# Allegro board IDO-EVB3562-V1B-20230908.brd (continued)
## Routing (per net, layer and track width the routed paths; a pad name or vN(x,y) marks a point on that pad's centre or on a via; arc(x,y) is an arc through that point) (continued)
LANWAKEB: length 6.4
  BOTTOM w0.127: U15.21 73.49,55.91 74.96,54.44 R161.2 74.48,53.47 74.48,52.64 74.29,52.44 74.29,51.74 74.61,51.41 R154.2
LCD_BL_PWM_GPIO0_B7_D: length 92.8
  TOP w0.127: M1.157 65.87,18.14 65.38,18.64 65.38,19.72 64.73,20.37 v1(63.44,20.37) ; v1(8.03,49.69) 10.57,47.15 10.57,44.1 10.32,43.85 8.54,43.85 7.91,43.21 v1(7.91,41.56) 7.6,41.25 R99.1
  BOTTOM w0.127: v1(63.44,20.37) 63.44,20.99 62.78,21.66 42.94,21.66 39.4,25.2 39.4,27.12 36.55,29.97 34.9,29.97 34.4,30.47 31.78,30.47 29.5,28.18 24.57,28.18 23.3,29.45 18.83,29.45 17.62,28.24 12.98,28.24 11.09,30.12 11.09,32.98 11.76,33.65 11.76,36.9 7.91,40.75 v1(7.91,41.56) ; v1(8.03,49.69) 8.03,48.73 R75.1
LCD_ON: length 15.2
  TOP w0.127: R453.1 8.41,42.9 8.41,41.41 8.15,41.15 8.15,40.17 7.9,39.91 7.33,39.91 R98.2 6.23,39.28 4.6,37.65 4.6,33.2 J43.4
LCD_PWM: length 8.9
  TOP w0.127: R99.2 6.69,40.1 4.1,37.5 4.1,34.69 J43.3
LCD_PWREN_H_GPIO0_B4_D: length 78.2
  TOP w0.127: v1(8.62,40.83) 8.62,40.27 7.62,39.28 R98.1 ; M1.154 62.87,18.55 63.12,18.8 v1(63.12,19.08)
  BOTTOM w0.127: v1(63.12,19.08) 63.12,19.31 63.91,20.09 63.91,20.88 62.88,21.91 43.05,21.91 39.66,25.3 39.66,27.22 36.66,30.22 35.01,30.22 34.51,30.72 31.68,30.72 29.39,28.43 24.68,28.43 23.4,29.71 18.73,29.71 17.51,28.49 13.08,28.49 11.35,30.22 11.35,32.88 12.01,33.54 12.01,37.01 8.62,40.4 v1(8.62,40.83)
LED0/PHYAD0: length 45.4
  TOP w0.127: v1(31.78,54.28) 31.31,54.76 31.31,56.82 33.21,58.72 33.21,68.14 35.36,70.29 35.36,71.18 35.14,71.41 33.75,71.41 C152.2 32.16,72.99 32.16,73.7 21.5,84.36 20.59,84.36 20.08,84.87 J23.11
  BOTTOM w0.127: v1(31.78,54.28) 31.78,53.37 31.53,53.12 R205.2 32.32,53.47 U17.24
LED1/GPO: length 53
  TOP w0.127: J21.13 59.98,84.8 59.98,79.18 55.91,75.11 55.91,68.68 C112.1 56.42,68.19 57.66,69.43 v1(57.66,69.6)
  BOTTOM w0.127: U15.26 71.3,57.45 70.48,56.63 70.48,55.62 70.11,55.25 68.9,55.25 68.23,54.57 65.59,54.57 65.12,55.05 65.12,58.71 67.28,60.87 67.28,65.18 66.32,66.14 65.6,66.14 64.45,67.29 59.96,67.29 v1(57.66,69.6)
LED1/PHYAD1: length 44.5
  TOP w0.127: v1(31.78,54.96) 31.78,56.93 33.46,58.61 33.46,68.03 35.62,70.19 35.62,72.02 35.21,72.42 33.75,72.42 R200.2 C150.1 32.27,73.95 25.94,80.28 25.94,84.87 27.85,86.77 29.85,86.77 J23.9
  BOTTOM w0.127: v1(31.78,54.96) 31.27,54.96 31.15,55.09 31.15,55.4 31.3,55.56 U17.25
LED2/LED1: length 53.3
  TOP w0.127: v1(66.49,65.31) 66.49,67.89 65.95,68.44 65.95,70.14 67.65,71.84 67.65,72.52 68.23,73.11 69.25,73.11 69.96,72.4 69.96,71.18 70.32,70.82 72.32,70.82 72.73,71.24 C113.1 72.73,72.21 66.17,78.77 66.17,82.13 67.11,83.06 J21.12
  BOTTOM w0.127: U15.25 71.26,57.05 70.73,56.53 70.73,55.51 70.22,55 69.01,55 68.33,54.32 65.49,54.32 64.87,54.94 64.87,58.81 67.03,60.97 67.03,64.77 v1(66.49,65.31)
MAC_MDC_: length 63.7
  BOTTOM w0.127: U17.22 33.32,52.9 33.56,52.66 33.56,50.56 34.02,50.1 35.67,50.1 38.54,47.23 43.86,47.23 49.99,41.1 61.4,41.1 66.43,46.14 76.21,46.14 77.25,47.18 77.25,47.62 78.81,49.18 78.81,50.55 79.09,50.83 80.55,50.83 81.37,51.65 C151.2 81.92,52.91 81.92,53.15 R203.2
MAC_MDIO: length 60.6
  BOTTOM w0.127: R202.2 79.76,49.72 79.76,48.88 79.41,48.52 79.41,48.39 77.85,46.84 77.37,46.84 76.36,45.83 66.56,45.83 61.53,40.8 49.83,40.8 43.68,46.95 38.41,46.95 35.57,49.79 33.84,49.79 33.08,50.55 33.08,52.51 32.91,52.68 R207.2 32.54,53.14 32.82,53.42 U17.23
MIC1_IN: length 95
  TOP w0.254: v1(92.11,37.5) 92.43,37.18 107.13,37.18 109.47,34.84 112.92,34.84 113.71,35.64 v1(120.81,35.64) ; C1049.2 88.18,36.17 v1(88.18,36.95) ; J36.1 v1(130.83,80.09)
  BOTTOM w0.254: v1(88.18,36.95) 88.18,37.38 88.42,37.62 91.68,37.62 91.81,37.5 v1(92.11,37.5) ; v1(120.81,35.64) 121.48,36.3 121.9,36.3 126.29,40.69 126.29,41.26 126.72,41.68 126.72,42.13 130.52,45.94 130.52,66.31 125.48,71.34 125.48,77.38 128.68,80.58 R388.2 129.26,82.13 129.29,82.1 D65.1 130.83,81.1 v1(130.83,80.09)
MIC2_IN: length 110.5
  TOP w0.254: v1(88.86,36.98) 88.86,36.97 88.86,35.83 C1050.2 ; v1(121.57,35.59) 121.09,35.11 113.8,35.11 113.11,34.42 109.23,34.42 106.92,36.74 91.48,36.74 v1(91.27,36.95) ; J37.1 116.18,87.33 115.63,86.77 115.63,74.76 114.49,73.62 D69.1 114.49,72.06 114.52,72.03 R387.2 114.52,68.28 114.94,67.85 130.06,67.85 v1(130.61,67.29)
  BOTTOM w0.254: v1(88.86,36.98) 88.89,36.95 v1(91.27,36.95) ; v1(130.61,67.29) 130.95,66.95 130.95,45.74 127.1,41.88 127.1,41.53 126.77,41.2 126.77,40.45 121.91,35.59 v1(121.57,35.59)
MIPI_CSI1_RX0_D2N: length 31.4
  TOP w0.102: v1(19.86,5) 19.58,5.29 19.58,5.78 19.71,5.9 J19.11
  BOTTOM w0.102: v1(19.86,5) 19.67,5.2 19.67,5.34 19.8,5.47 20.82,5.47 21.49,4.79 36.04,4.79 36.77,5.52 43.65,5.52 46.28,8.15 46.28,8.38 46.43,8.53 R1175.5
MIPI_CSI1_RX0_D2P: length 31.5
  TOP w0.102: J19.12 19.21,5.9 19.33,5.78 19.33,5.27 v1(19.06,5)
  BOTTOM w0.102: v1(19.06,5) 19.41,5.36 19.41,5.44 19.69,5.72 20.92,5.72 21.6,5.05 35.94,5.05 36.67,5.77 43.54,5.77 46.02,8.25 46.02,8.38 45.88,8.53 R1175.6
MIPI_CSI1_RX0_D3N: length 32.3
  TOP w0.102: v1(18.36,5.01) 18.08,5.28 18.08,5.78 18.21,5.9 J19.14
  BOTTOM w0.102: R1175.7 45.38,8.53 45.23,8.38 45.23,8.17 43.32,6.26 36.47,6.26 35.74,5.53 21.8,5.53 21.12,6.21 18.5,6.21 18.08,5.79 18.08,5.22 18.3,5.01 v1(18.36,5.01)
MIPI_CSI1_RX0_D3P: length 32.3
  TOP w0.102: v1(17.55,5.01) 17.83,5.28 17.83,5.78 17.71,5.9 J19.15
  BOTTOM w0.102: v1(17.55,5.01) 17.66,5.01 17.83,5.18 17.83,5.89 18.39,6.46 21.23,6.46 21.9,5.78 35.63,5.78 36.36,6.51 43.21,6.51 44.97,8.27 44.97,8.38 44.83,8.53 R1175.8
MIPI_CSI2_RX0_D2N: length 2.8
  TOP w0.102: J18.11 45.21,7.41 45.32,7.53 45.49,7.53 46.36,8.4 46.36,8.8 46.43,8.86 R1176.8
MIPI_CSI2_RX0_D2P: length 3
  TOP w0.102: J18.12 44.71,7.27 45.22,7.78 45.39,7.78 46.11,8.5 46.11,8.58 45.88,8.82 R1176.7
MIPI_CSI2_RX0_D3N: length 3.4
  TOP w0.102: J18.14 43.71,7.18 43.59,7.31 43.59,7.41 44.26,8.08 44.84,8.08 45.24,8.49 45.24,8.69 45.38,8.83 R1176.6
MIPI_CSI2_RX0_D3P: length 3.4
  TOP w0.102: J18.15 43.21,7.19 43.33,7.31 43.33,7.52 44.15,8.34 44.73,8.34 44.99,8.6 44.99,8.69 44.83,8.86 R1176.5
MIPI_CSI_RX0_CLK0N: length 13.1
  TOP w0.102: v1(48.29,7.7) 48.21,7.62 J18.5 ; M1.137 45.87,17.55 45.5,17.18 45.5,17.03 47.1,15.43 47.1,14.11 48.11,13.09 48.11,9.95 47.74,9.58 47.74,9.4 v1(48.02,9.13)
  BOTTOM w0.102: v1(48.02,9.13) 47.74,8.85 47.74,8.59 48.04,8.29 48.04,7.96 v1(48.29,7.7)
MIPI_CSI_RX0_CLK0P: length 13.1
  TOP w0.102: M1.136 44.87,17.55 45.24,17.18 45.24,16.93 46.85,15.33 46.85,14 47.86,12.99 47.86,10.06 47.49,9.68 47.49,9.4 v1(47.21,9.13) ; v1(47.53,7.7) 47.71,7.53 J18.6
  BOTTOM w0.102: v1(47.21,9.13) 47.49,8.85 47.49,8.48 47.78,8.18 47.78,7.96 v1(47.53,7.7)
MIPI_CSI_RX0_CLK1N: length 41.5
  TOP w0.102: J19.17 16.71,7.47 16.58,7.59 16.58,7.84 15.39,9.04 15.39,9.57 14.47,10.49 14.47,14.34 16.39,16.26 18.88,16.26 19.13,16.52 19.13,16.81 v1(19.38,17.06) ; v1(39.77,19.47) 39.5,19.2 39.5,18.68 39.87,18.31 M1.131
  BOTTOM w0.102: v1(39.77,19.47) 39.5,19.19 39.5,18.75 39.23,18.47 38.33,18.47 38.07,18.72 38.07,19.85 37.95,19.97 37.58,19.97 37.47,19.86 37.47,18.72 37.21,18.47 26.9,18.47 26.78,18.35 25.46,18.35 24.79,17.68 19.31,17.68 19.11,17.48 19.11,17.33 v1(19.38,17.06)
MIPI_CSI_RX0_CLK1P: length 41.5
  TOP w0.102: J19.18 16.21,7.47 16.33,7.59 16.33,7.74 15.14,8.93 15.14,9.47 14.22,10.38 14.22,14.45 16.29,16.52 18.77,16.52 18.88,16.62 18.88,16.76 v1(18.58,17.06) ; v1(38.97,19.47) 39.25,19.18 39.25,18.65 38.87,18.27 M1.130
  BOTTOM w0.102: v1(18.58,17.06) 18.85,17.33 18.85,17.58 19.21,17.94 24.69,17.94 25.35,18.6 26.67,18.6 26.8,18.73 37.11,18.73 37.21,18.83 37.21,19.96 37.47,20.23 38.06,20.23 38.33,19.95 38.33,18.83 38.43,18.73 39.12,18.73 39.24,18.85 39.24,19.19 v1(38.97,19.47)
MIPI_CSI_RX0_D0N: length 12.5
  TOP w0.102: J18.2 49.71,7.47 49.59,7.59 49.59,8.52 49.74,8.68 49.74,8.93 49.59,9.08 49.59,9.34 49.74,9.49 49.74,9.74 49.59,9.9 49.59,11.6 50.68,12.69 50.68,16.06 49.61,17.13 49.61,17.23 49.87,17.49 M1.141
MIPI_CSI_RX0_D0P: length 12.5
  TOP w0.102: J18.3 49.21,7.47 49.33,7.59 49.33,11.7 50.43,12.8 50.43,15.96 49.36,17.02 49.36,17.28 49.28,17.36 49,17.36 48.87,17.49 M1.140
MIPI_CSI_RX0_D1N: length 14.8
  TOP w0.102: J18.8 46.71,7.23 46.59,7.35 46.59,7.58 47.3,8.29 48.41,8.29 48.85,8.73 48.85,11.9 49.94,13 49.94,15.3 49.46,15.78 48.84,15.78 47.5,17.12 47.5,17.32 47.87,17.7 M1.139
MIPI_CSI_RX0_D1P: length 14.8
  TOP w0.102: J18.9 46.21,7.22 46.33,7.34 46.33,7.68 47.19,8.55 48.31,8.55 48.6,8.83 48.6,12.01 49.69,13.1 49.69,15.19 49.36,15.53 48.74,15.53 47.24,17.02 47.24,17.29 46.87,17.66 M1.138
MIPI_CSI_RX0_D2N: length 10.3
  TOP w0.102: M1.135 43.87,17.63 43.59,17.36 43.59,17.28 45.45,15.43 45.45,13.22 46.38,12.29 46.38,10.96 v1(46.64,10.7) 46.64,10.68 46.43,10.47 R1176.1
  BOTTOM w0.102: v1(46.64,10.7) 46.43,10.48 R1176.1
MIPI_CSI_RX0_D2P: length 10.3
  TOP w0.102: M1.134 42.87,17.62 43.11,17.38 43.26,17.38 43.34,17.3 43.34,17.18 45.19,15.32 45.19,13.11 46.13,12.18 46.13,10.96 45.87,10.7 v1(45.87,10.69) 45.85,10.69 45.88,10.67 R1176.2
  BOTTOM w0.102: v1(45.87,10.69) 45.88,10.68 R1176.2
MIPI_CSI_RX0_D3N: length 10.7
  TOP w0.102: R1176.3 45.38,10.32 45.12,10.57 v1(45.12,10.7) 44.86,10.95 44.86,11.82 42.3,14.39 42.3,15.91 41.38,16.82 41.38,17.23 41.87,17.72 M1.133
  BOTTOM w0.102: v1(45.12,10.7) 45.12,10.57 45.38,10.32 R1176.3
MIPI_CSI_RX0_D3P: length 10.8
  TOP w0.102: M1.132 40.87,17.69 41.13,17.43 41.13,16.72 42.04,15.8 42.04,14.28 44.61,11.72 44.61,10.95 v1(44.36,10.7) 44.36,10.57 44.83,10.1 R1176.4
  BOTTOM w0.102: v1(44.36,10.7) 44.36,10.57 44.83,10.1 R1176.4
MIPI_CSI_RX1_CLK0N: length 53.4
  TOP w0.102: v1(35.8,23.28) 35.98,23.28 36.08,23.38 36.08,23.71 36.18,23.81 36.65,23.81 36.75,23.71 36.75,23.33 36.9,23.19 37.57,23.19 ; J20.17 2.64,18.21 2.57,18.14 2.45,18.14 2.39,18.2 2.39,22.4 3.26,23.27 6.23,23.27 7.17,22.33 11.61,22.33 15.09,23.07 15.89,23.07 v1(16.16,22.79)
  BOTTOM w0.102: v1(16.16,22.79) 16.44,23.07 16.69,23.07 16.92,23.3 16.92,24.31 17.3,24.69 18.7,24.69 19.25,24.13 19.25,21.85 20.29,20.81 23.71,20.81 24.95,22.05 30.87,22.05 31.12,22.31 31.12,23.25 31.22,23.35 31.63,23.35 31.73,23.25 31.73,22.31 31.98,22.05 32.6,22.05 32.85,22.31 32.85,23.88 32.95,23.99 33.36,23.99 33.46,23.88 33.46,22.31 33.71,22.05 34.37,22.05 34.63,22.31 34.63,23.05 35.15,23.56 35.52,23.56 v1(35.8,23.28)
MIPI_CSI_RX1_CLK0P: length 53.4
  TOP w0.102: v1(35.8,24.09) 35.82,24.06 36.79,24.06 36.91,24.19 37.57,24.19 ; J20.15 2.62,17.81 2.55,17.89 2.35,17.89 2.14,18.1 2.14,22.51 3.15,23.53 6.34,23.53 7.28,22.59 11.58,22.59 15.06,23.32 15.89,23.32 v1(16.16,23.6)
  BOTTOM w0.102: v1(35.8,24.09) 35.52,23.81 35.04,23.81 34.38,23.15 34.38,22.42 34.27,22.31 33.81,22.31 33.71,22.41 33.71,23.99 33.46,24.24 32.85,24.24 32.6,23.99 32.6,22.41 32.49,22.31 32.09,22.31 31.99,22.41 31.99,23.36 31.74,23.61 31.12,23.61 30.87,23.36 30.87,22.41 30.77,22.31 24.85,22.31 23.6,21.06 20.4,21.06 19.5,21.96 19.5,24.24 18.8,24.94 17.19,24.94 16.67,24.42 16.67,23.4 16.59,23.32 16.44,23.32 v1(16.16,23.6)
MIPI_CSI_RX1_D0N: length 51.9
  TOP w0.102: 37.57,19.19 36.94,19.19 36.82,19.3 36.82,19.65 36.69,19.79 36.33,19.79 36.2,19.67 36.2,19.36 36.12,19.28 v1(35.8,19.28) ; J20.13 2.55,17.41 2.5,17.36 2.12,17.36 1.79,17.69 1.79,22.84 2.96,24.01 5.62,24.01 7.51,25.89 8.47,25.89 9.28,26.7 11.87,26.7 11.97,26.6 11.97,25.53 12.22,25.28 12.84,25.28 13.09,25.53 13.09,26.6 13.19,26.7 14.35,26.7 16.82,24.24 16.82,23.76 17.04,23.54 17.4,23.18 17.4,22.28 v1(17.13,22)
  BOTTOM w0.102: v1(35.8,19.28) 35.57,19.51 34.68,19.51 34.52,19.67 26.47,19.67 26.14,19.34 19.46,19.34 17.4,21.4 17.4,21.73 v1(17.13,22)
MIPI_CSI_RX1_D0P: length 52.2
  TOP w0.102: J20.11 2.59,17.01 2.5,17.1 2.01,17.1 1.53,17.58 1.53,22.94 2.85,24.26 5.52,24.26 7.4,26.15 8.37,26.15 9.18,26.96 11.98,26.96 12.23,26.71 12.23,25.64 12.33,25.53 12.73,25.53 12.84,25.64 12.84,26.71 13.09,26.96 14.46,26.96 17.08,24.34 17.08,23.86 17.66,23.28 17.66,22.28 v1(17.93,22) ; 37.57,20.19 37.1,20.19 36.96,20.05 35.84,20.05 v1(35.8,20.09)
  BOTTOM w0.102: v1(35.8,20.09) 35.8,19.85 35.72,19.77 34.78,19.77 34.63,19.92 26.37,19.92 26.04,19.59 19.57,19.59 17.66,21.5 17.66,21.73 v1(17.93,22)
MIPI_CSI_RX1_D1N: length 52.1
  TOP w0.102: J20.9 2.67,16.61 2.6,16.54 1.86,16.54 1.15,17.25 1.15,23.2 2.74,24.79 6.56,26 7.2,26.63 8.11,26.63 8.92,27.44 15.12,27.44 17.97,24.59 17.97,24.34 v1(17.7,24.06) ; v1(35.8,21.28) 36.02,21.28 36.12,21.39 36.12,21.67 36.25,21.8 36.58,21.8 36.7,21.68 36.7,21.28 36.79,21.19 37.57,21.19
  BOTTOM w0.102: v1(17.7,24.06) 17.97,23.79 17.97,23.5 18.51,22.26 18.51,21.55 19.99,20.07 24.01,20.07 25.26,21.32 35.16,21.32 35.4,21.56 35.52,21.56 v1(35.8,21.28)
MIPI_CSI_RX1_D1P: length 52.1
  TOP w0.102: v1(35.8,22.09) 35.83,22.05 36.76,22.05 36.89,22.19 37.57,22.19 ; J20.7 2.65,16.21 2.58,16.29 1.76,16.29 0.9,17.15 0.9,23.3 2.6,25.01 6.43,26.22 7.09,26.89 8,26.89 8.81,27.69 15.22,27.69 18.22,24.69 18.22,24.34 v1(18.5,24.06)
  BOTTOM w0.102: v1(18.5,24.06) 18.22,23.79 18.22,23.55 18.77,22.31 18.77,21.65 20.09,20.33 23.91,20.33 25.15,21.57 35.06,21.57 35.3,21.81 35.52,21.81 v1(35.8,22.09)
MIPI_CSI_RX1_D2N: length 51.8
  TOP w0.102: 37.57,25.19 37.14,25.19 36.89,25.43 35.95,25.43 v1(35.8,25.28) ; v1(21.47,22.38) 21.75,22.11 21.75,21.85 22,21.6 23.04,21.6 23.38,21.26 23.38,21.07 23.2,20.89 21.6,20.89 21.33,20.62 21.33,20.05 21.6,19.77 23.19,19.77 23.38,19.59 23.38,19.34 22.74,18.7 14.35,18.7 11.42,15.78 8.91,15.78 7.69,14.56 7.12,14.56 6.87,14.31 6.87,13.24 6.77,13.14 6.36,13.14 6.26,13.24 6.26,14.31 6.01,14.56 4.56,14.56 3.78,15.34 3.28,15.34 3.21,15.41 J20.3
  BOTTOM w0.102: v1(35.8,25.28) 35.52,25.56 35.39,25.56 34.61,24.77 32.01,24.77 31.33,24.09 30.61,24.09 29.31,22.79 24.65,22.79 23.4,21.55 22.1,21.55 21.75,21.9 21.75,22.11 v1(21.47,22.38)
MIPI_CSI_RX1_D2P: length 52.1
  TOP w0.102: 37.57,26.19 37.18,26.19 36.96,25.97 36.96,25.86 36.79,25.69 36.2,25.69 v1(35.8,26.09) ; J20.1 3.21,15.01 3.28,15.09 3.67,15.09 4.45,14.31 5.91,14.31 6.01,14.21 6.01,13.14 6.26,12.89 6.88,12.89 7.13,13.14 7.13,14.21 7.23,14.31 7.8,14.31 9.01,15.53 11.53,15.53 14.45,18.45 22.84,18.45 23.63,19.24 23.63,19.69 23.29,20.03 21.71,20.03 21.58,20.16 21.58,20.51 21.71,20.64 23.3,20.64 23.63,20.96 23.63,21.37 23.15,21.85 22.11,21.85 22,21.96 22,22.11 v1(22.28,22.38)
  BOTTOM w0.102: v1(22.28,22.38) 22,22.11 22,22 22.21,21.8 23.3,21.8 24.54,23.05 29.2,23.05 30.5,24.35 31.22,24.35 31.91,25.03 34.5,25.03 35.29,25.81 35.52,25.81 v1(35.8,26.09)
MIPI_CSI_RX1_D3N: length 51.8
  TOP w0.102: v1(35.8,27.28) 36.12,27.28 36.23,27.39 36.23,27.69 36.33,27.8 36.71,27.8 36.79,27.72 36.79,27.29 36.89,27.19 37.57,27.19 ; v1(20.08,22.8) 20.36,23.07 20.5,23.07 20.59,22.98 20.59,19.63 20.43,19.46 19.77,19.46 19.67,19.57 19.67,20 19.84,20.18 19.84,21.04 19.55,21.33 18.8,21.33 18.55,21.08 18.55,19.57 18.45,19.46 14.07,19.46 11.12,16.52 8.6,16.52 7.43,15.34 5.26,15.34 5.19,15.41 J20.4
  BOTTOM w0.102: v1(20.08,22.8) 20.36,23.07 21.75,23.07 22.2,23.53 22.66,23.53 23.3,22.89 23.71,22.89 24.34,23.53 29,23.53 31.21,25.73 31.21,26.93 31.35,27.08 31.73,27.08 31.83,26.97 31.83,25.76 32.08,25.51 32.7,25.51 32.95,25.76 32.95,26.87 33.05,26.97 33.46,26.97 33.56,26.87 33.56,25.82 33.81,25.56 34.35,25.56 34.67,25.88 34.67,26.83 35.41,27.56 35.52,27.56 v1(35.8,27.28)
MIPI_CSI_RX1_D3P: length 51.8
  TOP w0.102: 37.57,28.19 37.08,28.19 36.94,28.05 35.84,28.05 v1(35.8,28.09) ; v1(20.08,23.6) 20.36,23.33 20.61,23.33 20.84,23.09 20.84,19.52 20.53,19.21 19.67,19.21 19.41,19.46 19.41,20.1 19.59,20.28 19.59,20.93 19.44,21.08 18.91,21.08 18.81,20.98 18.81,19.46 18.55,19.21 14.17,19.21 11.22,16.26 8.71,16.26 7.53,15.09 5.26,15.09 5.19,15.01 J20.2
  BOTTOM w0.102: v1(20.08,23.6) 20.36,23.33 21.64,23.33 22.1,23.78 22.77,23.78 23.4,23.15 23.6,23.15 24.24,23.78 28.9,23.78 30.95,25.84 30.95,27.04 31.25,27.33 31.83,27.33 32.08,27.08 32.08,25.86 32.19,25.76 32.59,25.76 32.69,25.86 32.69,26.97 32.94,27.22 33.56,27.22 33.81,26.97 33.81,25.92 33.92,25.81 34.25,25.81 34.42,25.99 34.42,26.93 35.3,27.81 35.52,27.81 v1(35.8,28.09)
MIPI_DSI_RST: length 89.5
  TOP w0.127: v1(8.8,67.6) 11.14,65.25 14.04,65.25 16.54,62.75 16.54,62.14 16.78,61.89 18.24,61.89 19.34,60.8 19.34,59.34 18.57,58.58 17.54,58.58 17.43,58.47 D24.6 D24.5 15.51,58.47 15.4,58.58 15.4,58.83 15.54,58.97 D24.4 D24.7 18.46,58.97 18.96,59.47 18.96,60.82 18.13,61.64 16.66,61.64 16.29,62.01 16.29,62.64 13.93,65 11.23,65 10.62,64.4 10.62,63.7 v1(9.99,63.07) 9.61,63.07 9.4,62.86 7.94,62.86 7.7,62.62 J46.16 ; R78.1 v1(40.8,69.25)
  BOTTOM w0.127: v1(40.8,69.25) 38.71,69.25 35.53,72.42 33.16,72.42 29.08,76.5 20.98,76.5 13.11,68.64 9.84,68.64 v1(8.8,67.6) ; v1(9.99,63.07) 9.33,62.41 9.33,61.41 8.74,60.82 6.05,60.82 4.79,62.08 R444.1 C93.2
MIPI_DSI_TX_CLKN/LVDS_TX_CLKN: length 90.5
  TOP w0.102: v1(43.79,39.48) 43.54,39.74 43.3,39.74 43.16,39.59 43.16,38.72 42.28,37.84 42.28,34.71 40.92,33.35 40.92,26.05 44.04,22.93 51.66,22.93 54.18,20.41 55.06,20.41 55.5,19.97 55.5,18.94 55.87,18.56 M1.147 ; v1(18.47,57.02) 18.19,57.3 17.59,57.3 17.47,57.17 D21.4 D21.7 15.66,57.17 15.58,57.25 15.58,57.32 15.48,57.42 14.93,57.42 14.49,57.87 14.49,60.48 14.09,60.88 13.11,60.88 12.75,60.52 12.75,60.37 12.83,60.28 13.35,60.28 J16.15 12.85,60.01 12.75,59.91 12.75,59.43 12.22,58.91 12.01,58.91 11.09,58.91 10.44,58.26 9.82,58.26 R1186.1
  BOTTOM w0.102: v1(43.79,39.48) 43.52,39.75 43.27,39.75 43.03,39.99 43.03,40.22 42.56,40.69 42.17,40.69 40.49,42.37 39.45,42.37 39.2,42.63 39.2,43.11 39.1,43.21 38.69,43.21 38.59,43.11 38.59,42.63 38.34,42.37 37.47,42.37 35.92,43.93 21.82,43.93 19.76,45.99 19.76,56.47 18.94,57.3 18.74,57.3 v1(18.47,57.02)
MIPI_DSI_TX_CLKP/LVDS_TX_CLKP: length 90.7
  TOP w0.102: v1(18.47,57.83) 18.19,57.55 17.59,57.55 17.47,57.67 D21.5 D21.6 15.03,57.67 14.74,57.97 14.74,60.59 14.2,61.13 13,61.13 12.18,60.31 11.92,60.31 J16.16 12.39,60.01 12.49,59.91 12.49,59.54 12.12,59.16 12.12,59.16 10.98,59.16 10.33,58.52 9.82,58.52 R1187.1 ; M1.146 54.87,18.56 55.24,18.94 55.24,19.87 54.95,20.16 54.08,20.16 51.56,22.67 43.94,22.67 40.67,25.94 40.67,33.46 42.02,34.81 42.02,37.94 42.9,38.82 42.9,39.7 43.2,39.99 43.5,39.99 v1(43.79,40.28)
  BOTTOM w0.102: v1(43.79,40.28) 43.52,40.01 43.37,40.01 43.28,40.1 43.28,40.33 42.67,40.94 42.28,40.94 40.59,42.63 39.56,42.63 39.45,42.73 39.45,43.22 39.2,43.47 38.59,43.47 38.34,43.22 38.34,42.73 38.23,42.63 37.57,42.63 36.02,44.18 21.93,44.18 20.02,46.09 20.02,56.58 19.04,57.55 18.74,57.55 v1(18.47,57.83)
MIPI_DSI_TX_D0N/LVDS_TX_D0N: length 88.6
  TOP w0.102: v1(18.32,51.46) 18.04,51.73 17.59,51.73 17.47,51.61 D20.1 D20.10 15.62,51.61 15.49,51.73 15.11,51.73 14,52.84 13.04,52.84 12.75,52.55 12.75,52.39 12.86,52.28 13.35,52.28 J16.7 12.85,52.01 12.75,51.91 12.75,51.63 12.03,50.91 11.21,50.91 8.99,53.13 8.99,53.49 R1182.1 ; v1(43.42,38.16) 43.7,37.89 44.09,37.89 44.58,37.41 44.58,34.92 42.4,32.74 42.4,26.66 44.65,24.4 54.66,24.4 55.28,23.77 55.43,23.77 55.82,24.16 56.17,24.16 56.61,23.72 56.61,23.37 56.22,22.98 56.22,22.84 56.51,22.55 56.65,22.55 57.16,23.07 57.52,23.07 57.95,22.63 57.95,22.28 57.44,21.76 57.44,21.32 59.5,19.26 59.5,18.94 59.87,18.56 M1.151
  BOTTOM w0.102: v1(18.32,51.46) 18.04,51.73 17.9,51.73 17.79,51.63 17.79,50.6 18.55,49.84 18.55,45.48 22.11,41.92 25.63,41.92 26.42,42.71 35.41,42.71 36.96,41.16 38.82,41.16 42.08,37.89 43.15,37.89 v1(43.42,38.16)
MIPI_DSI_TX_D0P/LVDS_TX_D0P: length 88.4
  TOP w0.102: M1.150 58.87,18.56 59.24,18.94 59.24,19.16 57.19,21.21 57.19,21.87 57.7,22.38 57.7,22.52 57.41,22.81 57.27,22.81 56.75,22.3 56.4,22.3 55.96,22.73 55.96,23.09 56.35,23.48 56.35,23.62 56.06,23.91 55.92,23.91 55.53,23.52 55.18,23.52 54.55,24.15 44.55,24.15 42.14,26.55 42.14,32.85 44.32,35.03 44.32,37.3 43.99,37.63 43.7,37.63 v1(43.42,37.36) ; R1183.1 9.24,53.49 9.24,53.23 11.31,51.16 11.92,51.16 12.49,51.74 12.49,51.91 12.39,52.01 J16.8 11.92,52.31 12.15,52.31 12.94,53.09 14.11,53.09 15.21,51.99 15.49,51.99 15.62,52.11 D20.9 D20.2 17.47,52.11 17.59,51.99 18.04,51.99 v1(18.32,52.26)
  BOTTOM w0.102: v1(18.32,52.26) 18.04,51.99 17.79,51.99 17.53,51.73 17.53,50.49 18.29,49.74 18.29,45.38 22,41.66 25.73,41.66 26.52,42.46 35.31,42.46 36.86,40.9 38.71,40.9 41.98,37.63 43.15,37.63 v1(43.42,37.36)
MIPI_DSI_TX_D1N/LVDS_TX_D1N: length 89.3
  TOP w0.102: M1.149 57.87,18.56 57.5,18.94 57.5,19.64 56.46,20.68 56.2,20.68 55.95,20.68 55.66,20.96 55.66,21.11 56.11,21.55 56.11,21.91 55.6,22.42 55.24,22.42 54.92,22.1 54.78,22.1 54.49,22.39 54.49,22.53 54.81,22.85 54.81,23.21 54.35,23.66 44.35,23.66 41.66,26.35 41.66,33.05 43.47,34.86 43.47,35.57 v1(43.74,35.85) ; v1(18.32,52.98) 18.05,53.26 17.62,53.26 17.47,53.11 D20.4 D20.7 15.62,53.11 15.37,53.36 15.16,53.36 14.64,53.88 14.64,54.13 13.84,54.93 12.99,54.93 12.71,54.65 12.71,54.44 12.81,54.34 13.29,54.34 J16.9 12.85,54.01 12.75,53.91 12.75,53.59 12.03,52.86 11.21,52.86 10.69,53.38 10.54,53.75 10.54,54.16 10.16,56.28 9.95,56.48 9.82,56.48 R1184.1
  BOTTOM w0.102: v1(43.74,35.85) 43.47,36.12 43.47,36.43 43.17,36.74 42.2,36.74 38.51,40.42 36.66,40.42 35.11,41.97 26.72,41.97 25.93,41.18 21.8,41.18 17.81,45.18 17.81,49.54 17.05,50.29 17.05,53.12 17.2,53.26 18.05,53.26 v1(18.32,52.98)
MIPI_DSI_TX_D1P/LVDS_TX_D1P: length 89.4
  TOP w0.102: v1(18.32,53.79) 18.05,53.51 17.57,53.51 17.47,53.61 D20.5 D20.6 15.27,53.61 14.89,53.99 14.89,54.24 13.95,55.18 12.88,55.18 12.04,54.34 11.95,54.34 J16.10 12.39,54.01 12.49,53.91 12.49,53.69 11.92,53.12 11.31,53.12 10.9,53.52 10.79,53.8 10.79,54.18 10.39,56.4 10.05,56.74 9.82,56.74 R1185.1 ; v1(42.94,35.85) 43.21,35.57 43.21,34.96 41.41,33.15 41.41,26.25 44.24,23.41 54.24,23.41 54.56,23.1 54.56,22.96 54.24,22.64 54.24,22.28 54.67,21.85 55.03,21.85 55.35,22.17 55.49,22.17 55.85,21.8 55.85,21.66 55.41,21.21 55.41,20.86 55.84,20.42 56.2,20.42 56.35,20.42 57.24,19.53 57.24,18.94 56.87,18.56 M1.148
  BOTTOM w0.102: v1(18.32,53.79) 18.05,53.51 17.09,53.51 16.8,53.22 16.8,50.19 17.55,49.43 17.55,45.07 21.7,40.93 26.04,40.93 26.83,41.72 35,41.72 36.55,40.16 38.41,40.16 42.09,36.48 43.06,36.48 43.21,36.33 43.21,36.12 v1(42.94,35.85)
MIPI_DSI_TX_D2N/LVDS_TX_D2N: length 89.8
  TOP w0.102: R1188.1 9.5,59.86 9.74,60.1 9.84,60.1 v1(10.12,59.82) ; v1(18.32,55.52) 18.04,55.8 17.59,55.8 17.47,55.67 D21.1 D21.10 15.62,55.67 15.49,55.8 15.13,55.8 14.08,56.85 13.11,56.85 12.75,56.49 12.75,56.11 12.85,56.01 J16.11 ; v1(42.32,39.25) 42.05,39.53 41.79,39.53 41.54,39.28 41.54,35.01 40.19,33.66 40.19,25.74 43.74,22.19 51.23,22.19 53.5,19.93 53.5,18.94 53.87,18.56 M1.145
  BOTTOM w0.102: v1(10.12,59.82) 10.28,59.82 10.73,59.38 10.73,58.66 10.47,58.41 10.47,55.56 11.13,54.9 12.2,54.9 12.75,55.44 12.75,55.91 12.85,56.01 J16.11 ; v1(42.32,39.25) 42.05,39.53 41.13,39.53 40.52,40.14 40.52,40.72 40.7,40.9 40.7,41.05 40.41,41.33 40.27,41.33 40.12,41.18 39.47,41.18 39.02,41.64 37.16,41.64 35.61,43.19 25.74,43.19 25.64,43.09 25.64,42.83 25.39,42.58 24.77,42.58 24.52,42.83 24.52,43.09 24.42,43.19 24.02,43.19 23.91,43.09 23.91,42.83 23.66,42.58 23.05,42.58 22.8,42.83 22.8,43.09 22.69,43.19 21.52,43.19 19.03,45.68 19.03,55.5 18.73,55.8 18.59,55.8 v1(18.32,55.52)
MIPI_DSI_TX_D2P/LVDS_TX_D2P: length 90.3
  TOP w0.102: M1.144 52.87,18.56 53.24,18.94 53.24,19.82 51.13,21.94 43.63,21.94 39.93,25.64 39.93,33.76 41.29,35.12 41.29,39.38 41.69,39.78 42.05,39.78 v1(42.32,40.06) ; v1(10.12,60.63) 9.84,60.35 9.76,60.35 R1189.1 ; v1(18.32,56.33) 18.04,56.05 17.59,56.05 17.47,56.18 D21.2 D21.9 15.62,56.18 15.49,56.05 15.24,56.05 14.18,57.11 13.01,57.11 12.49,56.59 12.49,56.28 12.22,56.01 J16.12
  BOTTOM w0.102: v1(42.32,40.06) 42.05,39.78 41.23,39.78 40.77,40.24 40.77,40.62 40.96,40.8 40.96,41.15 40.52,41.59 40.17,41.59 40.01,41.43 39.58,41.43 39.12,41.89 37.27,41.89 35.72,43.45 25.64,43.45 25.39,43.2 25.39,42.93 25.29,42.83 24.88,42.83 24.78,42.93 24.78,43.2 24.53,43.45 23.91,43.45 23.66,43.2 23.66,42.93 23.56,42.83 23.15,42.83 23.05,42.93 23.05,43.2 22.8,43.45 21.62,43.45 19.28,45.79 19.28,55.61 18.84,56.05 18.59,56.05 v1(18.32,56.33) ; v1(10.12,60.63) 10.13,60.63 10.73,60.03 10.73,59.74 10.98,59.48 10.98,58.55 10.73,58.3 10.73,55.66 11.24,55.15 12.1,55.15 12.49,55.55 12.49,55.82 12.31,56.01 J16.12
MIPI_DSI_TX_D3N/LVDS_TX_D3N: length 90.3
  TOP w0.102: v1(18.32,59.82) 18.04,60.09 17.59,60.09 17.47,59.97 D24.9 D24.2 15.81,59.97 15.69,60.09 15.47,60.09 15.22,60.34 15.22,61.83 14.16,62.89 12.86,62.89 12.63,62.66 12.63,62.49 12.78,62.34 13.29,62.34 J16.17 12.85,62.01 12.75,61.91 12.75,61.56 12.05,60.87 11.18,60.87 10.23,61.82 9.82,61.82 R1190.1 ; v1(43.47,41.22) 43.19,41.49 41.87,41.49 40.69,40.31 40.69,35.37 39.45,34.12 39.45,25.44 43.54,21.34 50.35,21.34 51.5,20.2 51.5,18.94 51.87,18.56 M1.143
  BOTTOM w0.102: v1(43.47,41.22) 43.19,41.49 42.41,41.49 40.5,43.4 40.08,43.4 39.44,44.04 36.84,44.04 36.22,44.67 22.74,44.67 20.5,46.91 20.5,56.91 19.72,57.69 19.72,59.67 19.29,60.09 18.59,60.09 v1(18.32,59.82)
MIPI_DSI_TX_D3P/LVDS_TX_D3P: length 90.3
  TOP w0.102: v1(43.47,42.02) 43.19,41.75 41.77,41.75 40.44,40.42 40.44,35.47 39.2,34.23 39.2,25.33 43.44,21.09 50.25,21.09 51.24,20.09 51.24,18.94 50.87,18.56 M1.142 ; v1(18.32,60.62) 18.04,60.35 17.59,60.35 17.47,60.47 D24.10 D24.1 15.84,60.47 15.72,60.35 15.58,60.35 15.48,60.45 15.48,61.93 14.26,63.14 12.76,63.14 J16.18 12.39,62.01 12.49,61.91 12.49,61.67 11.95,61.12 11.29,61.12 10.34,62.07 9.82,62.07 R1191.1
  BOTTOM w0.102: v1(18.32,60.62) 18.59,60.35 19.4,60.35 19.97,59.77 19.97,57.8 20.76,57.01 20.76,47.01 22.85,44.92 36.33,44.92 36.95,44.3 39.54,44.3 40.18,43.65 40.61,43.65 42.52,41.75 43.19,41.75 v1(43.47,42.02)
MIPI_TX_BL_PWM: length 2.3
  BOTTOM w0.127: U10.4 7.21,50.32 7.21,50.32 R82.2 7.21,49.44 7.27,49.38 R75.2
MIPI_TX_CLKN: length 2.4
  TOP w0.102: J46.8 7.34,58.62 7.47,58.74 7.62,58.74 8.08,58.28 8.27,58.28 R1186.2
MIPI_TX_CLKP: length 2.4
  TOP w0.102: J46.9 7.34,59.12 7.47,58.99 7.72,58.99 8.18,58.53 8.3,58.53 R1187.2
MIPI_TX_D0N: length 3.3
  TOP w0.102: R1182.2 8.99,55.03 8.99,55.18 8.88,55.28 7.8,55.28 7.34,55.74 7.23,55.74 7.1,55.62 J46.2
MIPI_TX_D0P: length 3.7
  TOP w0.102: R1183.2 9.24,55.03 9.24,55.28 8.99,55.53 7.91,55.53 7.45,55.99 7.19,55.99 7.07,56.12 J46.3
MIPI_TX_D1N: length 2.7
  TOP w0.102: R1184.2 8.3,56.47 8,56.47 7.7,56.77 7.7,57.08 7.54,57.24 7.33,57.24 7.2,57.12 J46.5
MIPI_TX_D1P: length 2.7
  TOP w0.102: J46.6 7.22,57.62 7.34,57.49 7.65,57.49 7.96,57.18 7.96,56.88 8.11,56.73 8.27,56.73 R1185.2
MIPI_TX_D2N: length 2.6
  TOP w0.102: R1188.2 8.6,59.97 8.48,60.09 7.87,60.09 7.59,60.36 7.4,60.36 7.16,60.12 J46.11
MIPI_TX_D2P: length 2.3
  TOP w0.102: R1189.2 8.33,60.35 7.97,60.35 7.7,60.62 J46.12
MIPI_TX_D3N: length 2.2
  TOP w0.102: J46.14 7.26,61.62 7.38,61.74 7.74,61.74 7.81,61.81 8.3,61.81 R1190.2
MIPI_TX_D3P: length 2.3
  TOP w0.102: J46.15 6.57,62.12 7.24,62.12 7.36,61.99 7.63,61.99 7.7,62.06 8.27,62.06 R1191.2
PCIE20_0_TXN: length 22.6
  BOTTOM w0.114: U15.14 76.22,57.85 76.3,57.93 81.25,57.93 82.38,59.06 82.38,62.15 82.09,62.44 82.09,64.81 84.35,67.08 87.84,67.08 87.97,66.95 88.31,66.95 88.44,67.08 88.78,67.08 89.26,66.6 89.26,65.94 89.18,65.86 C317.2
PCIE20_0_TXP: length 22.6
  BOTTOM w0.114: U15.13 76.22,58.25 76.3,58.17 81.15,58.17 82.14,59.16 82.14,62.05 81.85,62.34 81.85,64.91 84.25,67.32 88.88,67.32 89.5,66.7 89.5,66.08 C319.2
PCIE20_32KHZ: length 4.1
  TOP w0.127: v1(95.52,44.62) 95.52,42.37 R342.2
  BOTTOM w0.127: v1(95.52,44.62) J27.68
PCIE20_CLKREQN: length 2.7
  TOP w0.127: R258.2 v1(95.92,39.91)
  BOTTOM w0.127: v1(95.92,39.91) 95.21,40.62 J27.52
PCIE20_CLKREQN_M1: length 77.2
  TOP w0.127: v1(75.83,43.47) 75.83,43.49 75.51,43.81 75.51,48.17 78.18,50.84 78.18,56.63 80.68,59.12 v1(80.68,60.22) ; R258.1 93.57,39.91 R308.1 93.18,39.53 92.46,40.25 v1(92.44,40.25) ; M1.72 52.87,61.88 53.12,61.63 53.69,61.63 54.23,61.09 57.81,61.09 60.59,58.3 61.91,58.3 62.14,58.07 62.14,57.54 62.03,57.43 62.03,55.92 64.96,53 64.96,51.93 68.53,48.36 v1(68.53,43.47)
  BOTTOM w0.127: v1(68.53,43.47) v1(75.83,43.47) 78.01,41.28 84.1,41.28 86.62,38.77 88.76,38.77 89.72,39.72 91.92,39.72 v1(92.44,40.25) ; v1(80.68,60.22) 80.68,59.67 R155.1
PCIE20_PERSTN: length 3.1
  TOP w0.127: R260.2 v1(95.92,38.89)
  BOTTOM w0.127: v1(95.92,38.89) 95.41,39.4 95.41,39.78 95.08,40.12 J27.50
PCIE20_PERSTN_M1: length 73.6
  TOP w0.127: M1.74 50.87,61.95 50.4,61.48 49.97,61.48 49.66,61.17 49.66,60.55 49.94,60.27 52.14,60.27 52.52,59.89 56.62,59.89 63.85,52.66 63.85,51 v1(65.01,49.84) 65.01,48.34 66.56,46.79 66.56,43.36 67.3,42.62 67.3,41.99 v1(67.85,41.43) ; v1(92.81,37.84) 93.19,38.22 R311.1 93.57,38.89 R260.1
  BOTTOM w0.127: v1(92.81,37.84) 92.64,38 86.27,38 83.75,40.52 77.53,40.52 76.61,41.43 75.47,41.43 75.22,41.69 68.1,41.69 v1(67.85,41.43) ; R153.1 75.78,50.51 74.32,49.05 66.42,49.05 65.64,49.84 v1(65.01,49.84)
PCIE20_REFCLKN: length 9.3
  TOP w0.102: R408.1 88.66,49.12 88.74,49.04 88.74,47.37 87.99,46.62 83.19,46.62 82.62,47.19 M1.29
PCIE20_REFCLKN_: length 21.9
  TOP w0.102: v1(88.27,47.66) 88.3,47.68 R408.2
  BOTTOM w0.102: v1(88.27,47.66) 88.98,48.37 90.05,48.37 90.56,47.86 92.28,47.86 94.95,48.76 96.72,48.76 98.13,47.35 98.13,44.98 100.4,42.7 101.54,42.7 102.34,41.9 102.34,41.24 102.09,40.99 101.84,40.99 101.72,40.87 J27.53
PCIE20_REFCLKP: length 9.3
  TOP w0.102: M1.28 82.79,46.19 82.96,46.36 88.1,46.36 89,47.26 89,48.67 R403.1
PCIE20_REFCLKP_: length 21.9
  TOP w0.102: R407.2 89.71,48.22 89.84,48.1 89.84,47.77 89.72,47.66 v1(89.47,47.66)
  BOTTOM w0.102: v1(89.47,47.66) 89.24,47.43 89.13,47.43 88.85,47.7 88.85,47.88 89.09,48.12 89.95,48.12 90.45,47.61 92.33,47.61 94.99,48.5 96.62,48.5 97.87,47.25 97.87,44.88 100.3,42.45 101.43,42.45 102.09,41.79 102.09,41.35 101.98,41.24 101.84,41.24 101.72,41.37 J27.55
PCIE20_RXDN: length 25.4
  TOP w0.114: v1(90.23,46.39) 90.51,46.11 90.51,44.86 89.8,44.16 88.06,44.16 R406.2
  BOTTOM w0.114: J27.41 99.97,37.87 99.84,38 99.62,38 96.76,40.86 96.76,41.35 95.33,42.78 93.31,42.78 93.01,42.48 93.01,41.82 92.31,41.13 91.14,41.13 90.65,40.63 90.09,40.63 89.76,40.96 89.76,41.52 90.51,42.27 90.51,46.11 v1(90.23,46.39)
PCIE20_RXDP: length 25.4
  TOP w0.114: v1(91.03,46.39) 90.75,46.11 90.75,44.76 89.9,43.92 88.06,43.92 R405.2
  BOTTOM w0.114: J27.43 100.01,38.37 99.88,38.24 99.72,38.24 97,40.96 97,41.45 95.43,43.02 93.21,43.02 92.76,42.58 92.76,41.92 92.21,41.37 91.04,41.37 90.55,40.87 90.19,40.87 90,41.06 90,41.42 90.75,42.17 90.75,46.11 v1(91.03,46.39)
PCIE20_TXDN: length 25.6
  TOP w0.114: v1(91.36,45.12) 91.64,44.84 91.64,44.71 89.31,42.38 88.06,42.38 C354.1
  BOTTOM w0.114: v1(91.36,45.12) 91.64,44.84 91.64,44.51 91.24,44.11 91.24,42.2 91.54,41.9 91.97,41.9 92.27,42.21 92.27,43.39 92.4,43.52 95.64,43.52 95.97,43.18 96.33,43.18 96.65,43.5 96.81,43.5 97.09,43.22 97.09,43.06 96.77,42.74 96.77,42.38 97.19,41.96 97.55,41.96 98.1,42.51 98.26,42.51 98.54,42.23 98.54,42.07 98.01,41.54 98.01,41.19 98.43,40.77 98.8,40.77 99.09,41.06 99.25,41.06 99.53,40.78 99.53,40.62 99.33,40.42 99.33,39.75 99.58,39.5 99.89,39.5 100.02,39.37 J27.47
PCIE20_TXDP: length 25.6
  TOP w0.114: v1(92.16,45.12) 91.88,44.84 91.88,44.61 89.41,42.14 88.06,42.14 C353.1
  BOTTOM w0.114: v1(92.16,45.12) 91.88,44.84 91.88,44.41 91.49,44.01 91.49,42.3 91.64,42.15 91.87,42.15 92.03,42.31 92.03,43.49 92.3,43.76 95.74,43.76 96.07,43.43 96.23,43.43 96.55,43.74 96.91,43.74 97.33,43.32 97.33,42.96 97.01,42.64 97.01,42.48 97.29,42.2 97.45,42.2 98,42.75 98.36,42.75 98.78,42.33 98.78,41.97 98.25,41.44 98.25,41.29 98.53,41.01 98.7,41.01 98.99,41.3 99.35,41.3 99.77,40.88 99.77,40.52 99.58,40.32 99.58,39.85 99.68,39.74 99.88,39.74 100.01,39.87 J27.49
PCIE20_WAKEN: length 2.5
  TOP w0.127: R259.2 v1(95.92,40.93)
  BOTTOM w0.127: v1(95.92,40.93) 95.73,41.12 J27.54
PCIE20_WAKEN_M1: length 69.8
  TOP w0.127: v1(93.12,40.25) 93.19,40.32 R310.1 R259.1 ; M1.73 51.87,62.14 52.63,61.37 53.58,61.37 54.13,60.83 56.04,60.83 64.1,52.77 64.1,51.4 v1(64.99,50.52) 65.07,50.52 66.82,48.77 66.82,47.63 66.82,43.48 67.77,42.54 v1(67.77,42.2)
  BOTTOM w0.127: v1(67.77,42.2) 68.27,42.7 75.72,42.7 77.66,40.77 83.89,40.77 86.41,38.26 91.13,38.26 v1(93.12,40.25) ; v1(64.99,50.52) 65.31,50.52 66.53,49.3 74.2,49.3 74.96,50.07 R154.1
PCIE_0_RXN: length 24.5
  BOTTOM w0.114: R402.2 86.74,66.06 86.74,66.22 86.62,66.34 85.6,66.34 85.47,66.21 85.13,66.21 85,66.34 84.66,66.34 82.82,64.5 82.82,62.75 84.48,61.09 84.48,57.1 83.61,56.23 81.45,56.23 81.36,56.14 76.47,56.14 75.82,55.49 75.15,55.49 74.77,55.88 74.77,56.05 74.69,56.13 U15.18
PCIE_0_RXP: length 24.5
  BOTTOM w0.114: U15.17 75.09,56.12 75.01,56.04 75.01,55.98 75.25,55.74 75.72,55.74 76.37,56.38 81.26,56.38 81.35,56.47 83.51,56.47 84.24,57.2 84.24,60.99 82.58,62.65 82.58,64.6 84.56,66.58 86.72,66.58 R401.2
PDM_CLK0_M0: length 95.5
  TOP w0.127: v1(63.46,2.45) 60.73,5.18 J45.3 ; v1(95.03,7.31) 95.45,6.89 95.89,6.89 96.38,7.39 96.38,7.67 96.92,8.2 97.62,8.2 99.24,9.82 104.87,9.82 106.62,11.57 106.62,16.9 107.98,18.26 107.98,28.28 102.12,34.15 91.47,34.15 90.47,35.15 90.47,37.71 R308.2
  BOTTOM w0.127: v1(95.03,7.31) 94.75,7.03 85.27,7.03 84.31,6.07 75.77,6.07 75.16,5.46 72.61,5.46 71.16,4.01 67.98,4.01 66.86,2.9 63.92,2.9 v1(63.46,2.45)
PDM_SDI1_M0: length 96.7
  TOP w0.127: R311.2 91.9,38.51 90.76,37.37 90.76,35.42 91.75,34.42 102.2,34.42 108.24,28.39 108.24,18.15 106.87,16.79 106.87,11.46 104.98,9.57 99.34,9.57 97.73,7.95 97.02,7.95 96.86,7.78 v1(96.86,7.48) ; v1(61.81,2.45) 58.73,5.53 J45.5
  BOTTOM w0.127: v1(61.81,2.45) 62.77,3.41 66.65,3.41 67.77,4.52 70.95,4.52 72.4,5.97 74.81,5.97 75.42,6.58 84.1,6.58 85.06,7.53 94.24,7.53 94.73,8.03 95.41,8.03 95.6,7.83 96.51,7.83 v1(96.86,7.48)
PDM_SDI2_M0: length 97.6
  TOP w0.127: v1(62.57,2.45) 62.07,2.95 62.07,2.98 59.73,5.31 J45.4 ; R310.2 91.35,39.98 91.35,39.13 90.18,37.96 90.18,34.88 91.19,33.87 102.04,33.87 107.73,28.18 107.73,18.36 106.37,17 106.37,11.67 104.77,10.07 99.13,10.07 97.52,8.46 96.8,8.46 v1(95.71,7.37)
  BOTTOM w0.127: v1(95.71,7.37) 95.3,7.77 94.84,7.77 94.35,7.28 85.16,7.28 84.21,6.33 75.54,6.33 74.93,5.72 72.51,5.72 71.06,4.27 67.87,4.27 66.76,3.15 63.28,3.15 v1(62.57,2.45)
PERSTB: length 7
  BOTTOM w0.127: U15.19 74.29,55.9 75.17,55.02 75.92,55.02 C318.2 76.46,53.42 76.46,52.64 75.98,52.15 R153.2
PHY0_CLKOUT125: length 5.1
  BOTTOM w0.127: U16.35 51.57,57.11 51.16,57.52 50.51,57.52 50.24,57.25 50.24,56.86 50.71,56.4 50.71,55.89 50.1,55.28 R170.2
PHY0_LED0/CFG_EXT: length 3.2
  BOTTOM w0.127: R174.2 49.74,54.26 51.39,55.91 U16.32
PHY0_LED1/CFG_LDO0: length 46.9
  TOP w0.127: J22.14 40.16,82.51 40.16,79.41 36.1,75.34 C133.2 R176.2 37.12,69.84 v1(37.28,70.01) ; v1(51.21,56.45) 51.21,57.31 50.96,57.56 49.94,57.56 49.44,58.07 49.44,58.81 48.21,60.03 45.85,60.03 v1(44.63,61.25)
  BOTTOM w0.127: U16.33 51.35,56.31 v1(51.21,56.45) ; v1(37.28,70.01) 41.98,65.31 43.47,65.31 44.84,63.94 44.84,61.46 v1(44.63,61.25)
PHY0_LED2/CFG_LDO1: length 50.9
  TOP w0.127: v1(50.71,57.06) 50.09,57.06 49.18,57.97 49.18,58.7 48.11,59.78 45.03,59.78 v1(44.23,60.57) ; v1(50.05,69.37) 50.4,69.37 C131.2 R175.1 52.18,68.61 52.18,69.63 52.61,70.06 54.4,70.06 55.05,70.71 55.05,72.85 52.56,75.34 50.36,75.34 46.62,79.09 46.62,82.13 47.55,83.06 J22.12
  BOTTOM w0.127: U16.34 51.61,56.71 51.26,57.06 v1(50.71,57.06) ; v1(44.23,60.57) 44.74,60.57 45.37,61.2 45.37,61.75 45.53,61.91 45.53,66.99 47.91,69.37 v1(50.05,69.37)
PHY0_MDI0+: length 4.2
  BOTTOM w0.102: R169.1 51.16,62.37 51.16,61.95 51.61,61.51 51.61,60.55 51.93,60.23 52.56,60.23 52.66,60.13 52.66,60.03 52.59,59.95 U16.1
PHY0_MDI0-: length 4.2
  BOTTOM w0.102: U16.2 52.99,59.98 52.92,60.05 52.92,60.23 52.66,60.48 52.03,60.48 51.86,60.66 51.86,61.62 51.42,62.06 51.42,62.4 R168.1
PHY0_MDI1+: length 3.5
  BOTTOM w0.102: R167.1 53.18,62.38 53.18,62.09 53.86,61.41 53.86,60.23 53.79,60.16 U16.4
PHY0_MDI1-: length 3.5
  BOTTOM w0.102: R166.1 53.44,62.38 53.44,62.2 54.12,61.52 54.12,60.23 54.19,60.16 U16.5
PHY0_MDI2+: length 3.4
  BOTTOM w0.102: U16.6 54.59,60.16 54.66,60.23 54.66,61.75 55.09,62.18 55.09,62.38 R165.1
PHY0_MDI2-: length 3.4
  BOTTOM w0.102: U16.7 54.99,60.15 54.92,60.22 54.92,61.65 55.34,62.07 55.34,62.38 R164.1
PHY0_MDI3+: length 4.1
  BOTTOM w0.102: U16.9 55.79,59.98 55.86,60.05 55.86,60.31 56.17,60.61 56.68,60.61 57.37,61.31 57.37,62.38 R163.1
PHY0_MDI3-: length 4.1
  BOTTOM w0.102: R162.1 57.63,62.38 57.63,61.21 56.78,60.36 56.27,60.36 56.12,60.2 56.12,60.03 56.19,59.95 U16.10
PHY0_RXCLK/PHYAD1: length 3.5
  BOTTOM w0.127: U16.27 53.79,54.4 53.83,54.36 53.83,53.01 54.01,52.84 R179.2 R192.1
PHY0_XTALIN: length 6.4
  BOTTOM w0.127: XT3.3 47.45,57.56 49.25,57.56 C129.2 50.09,57.78 51.26,57.78 51.53,57.51 U16.36
PHY0_XTALOUT: length 4.2
  BOTTOM w0.127: U16.37 51.49,57.91 51.37,58.03 49.92,58.03 C128.2 48.93,59.02 XT3.1
PHY2_MDI0+: length 4.2
  BOTTOM w0.102: U15.1 72.29,60.76 72.37,60.83 72.37,60.94 72.06,61.25 71.05,61.25 70.06,62.24 70.06,62.65 R145.1
PHY2_MDI0-: length 4.2
  BOTTOM w0.102: R144.1 70.31,62.63 70.31,62.34 71.16,61.5 72.17,61.5 72.62,61.05 72.62,60.82 72.69,60.75 U15.2
PHY2_MDI1+: length 3
  BOTTOM w0.102: R149.1 72.74,62.64 72.74,62.33 73.57,61.5 73.57,60.84 73.49,60.77 U15.4
PHY2_MDI1-: length 3
  BOTTOM w0.102: U15.5 73.89,60.77 73.82,60.84 73.82,61.61 72.99,62.43 72.99,62.64 R148.1
PHY2_MDI2+: length 2.8
  BOTTOM w0.102: U15.6 74.29,60.78 74.37,60.85 74.37,62.15 74.65,62.43 74.65,62.64 R142.1
PHY2_MDI2-: length 2.8
  BOTTOM w0.102: U15.7 74.69,60.78 74.62,60.85 74.62,62.05 74.9,62.33 74.9,62.64 R141.1
PHY2_MDI3+: length 4.5
  BOTTOM w0.102: U15.9 76.05,59.85 76.13,59.78 76.24,59.78 77.31,60.86 77.31,62.86 77.22,62.96 R147.1
PHY2_MDI3-: length 4.7
  BOTTOM w0.102: R140.1 77.57,62.64 77.57,60.75 76.34,59.53 76.11,59.53 76.04,59.45 U15.10
PHY2_MDI_0+: length 18
  BOTTOM w0.102: R145.2 70.07,64.17 70.07,66.5 70.8,67.22 70.8,67.72 D34.4 70.8,68.14 70.8,68.71 70.35,69.16 69.51,69.16 67.95,70.72 65.64,70.72 64.93,71.43 64.93,72.8 65.54,73.41 66.87,73.41 66.97,73.31 67.41,73.31 67.7,73.9 J21.2
PHY2_MDI_0-: length 18
  BOTTOM w0.102: J21.3 66.49,71.89 66.94,72.04 67.32,72.56 67.32,72.91 67.22,73.01 66.91,73.01 66.76,73.16 65.64,73.16 65.18,72.7 65.18,71.54 65.75,70.98 68.06,70.98 69.62,69.42 70.45,69.42 71.05,68.82 71.05,67.11 70.33,66.39 70.33,65.49 D34.3 70.33,64.97 70.33,64.17 R144.2
PHY2_MDI_1+: length 27.6
  BOTTOM w0.102: J21.4 64.04,74.58 63.02,73.57 61.63,73.57 61.25,73.95 61.25,75.04 61.83,75.62 67.97,75.62 69.91,73.69 69.91,71 71.61,69.3 72.27,69.3 72.73,68.84 72.73,68.17 D34.6 72.73,67.69 72.73,66.52 71.99,65.78 71.99,64.57 72.22,64.35 72.67,64.35 72.73,64.29 72.73,64.16 R149.2
PHY2_MDI_1-: length 27.7
  BOTTOM w0.102: J21.7 61.48,72.04 62.22,72.79 62.22,73.2 62.11,73.31 61.52,73.31 60.99,73.84 60.99,75.14 61.73,75.88 68.08,75.88 70.16,73.79 70.16,71.11 71.72,69.55 72.37,69.55 72.98,68.94 72.98,66.41 72.25,65.67 72.25,65.47 D34.1 72.25,64.99 72.25,64.68 72.33,64.6 72.78,64.6 72.98,64.39 72.98,64.18 R148.2
PHY2_MDI_2+: length 25.1
  TOP w0.102: J21.5 63.05,72.25 62.81,72.73 62.94,73.13 63.3,73.31 63.79,73.79 63.79,75.14 64.25,75.6 68,75.6 71.13,72.47 71.13,72.22 v1(70.85,71.94)
  BOTTOM w0.102: R142.2 74.66,64.19 74.66,66.66 75.39,67.39 75.39,67.69 D33.4 75.39,68.17 75.39,68.84 73.59,70.64 71.84,70.64 71.13,71.36 71.13,71.67 v1(70.85,71.94)
PHY2_MDI_2-: length 25.2
  TOP w0.102: J21.6 62.92,73.52 63.06,73.47 63.15,73.52 63.53,73.9 63.53,75.24 64.14,75.85 68.1,75.85 71.38,72.58 71.38,72.22 v1(71.66,71.94)
  BOTTOM w0.102: v1(71.66,71.94) 71.38,71.67 71.38,71.46 71.94,70.9 73.7,70.9 75.65,68.95 75.65,67.29 74.91,66.55 74.91,65.47 D33.3 74.91,64.99 74.91,64.16 R141.2
PHY2_MDI_3+: length 32.5
  BOTTOM w0.102: R147.2 77.33,64.19 77.33,64.27 77.27,64.32 76.86,64.32 76.56,64.62 76.56,65.92 77.3,66.66 77.3,67.67 77.06,67.92 D33.6 77.3,68.17 77.3,68.37 73.63,72.04 72.6,72.04 68.28,76.36 60.08,76.36 58.83,75.11 58.83,73.79 59.18,73.44 59.81,73.13 60.22,73.27 60.41,73.65 60.15,74.43 J21.8
PHY2_MDI_3-: length 32.2
  BOTTOM w0.102: J21.9 59.11,73.11 59.09,73.18 59.08,73.18 58.58,73.69 58.58,75.22 59.98,76.61 68.38,76.61 72.7,72.3 73.73,72.3 77.55,68.47 77.55,66.55 76.82,65.82 76.82,65.47 D33.1 76.82,64.99 76.82,64.73 76.97,64.57 77.38,64.57 77.58,64.37 77.58,64.16 R140.2
PHY2_XTALIN: length 6.8
  BOTTOM w0.127: U15.28 71.39,58.25 C116.1 69.44,56.93 67.26,56.93 XT2.3
PHY2_XTALOUT: length 4.3
  BOTTOM w0.127: U15.29 71.4,58.65 70.5,57.75 C115.1 68.5,57.75 XT2.1
PHY_INT: length 2.4
  BOTTOM w0.127: U17.11 37.87,58.06 38.26,58.45 R195.1
PMIC_32KOUT_WIFI: length 54.5
  TOP w0.127: v1(98.53,48.47) 95.89,48.47 94.93,47.51 94.93,42.67 R342.1 92.49,41.94 90.82,40.27 90.82,39.32 89.38,37.88 87.79,37.88 84.1,34.19 M1.16 ; v1(103.48,33.98) 103.48,33.95 108.69,28.74 108.69,26.56 R243.1 R391.1
  BOTTOM w0.127: v1(103.48,33.98) 103.07,34.39 103.07,42.27 102.07,43.28 100.64,43.28 98.7,45.22 98.7,48.31 v1(98.53,48.47)
PMIC_EXT_EN: length 142.3
  TOP w0.127: v1(96.79,8.92) 97.62,8.92 99.03,10.33 104.66,10.33 106.11,11.78 106.11,17.11 107.47,18.47 107.47,26.49 106.88,27.08 R1171.1 ; v1(16.29,43.47) 16.29,44.17 R4.1 ; v1(77.07,19.99) 77.23,20.15 79.71,20.15 80.42,20.86 80.42,25.31 81.3,26.19 M1.8 ; v1(26.87,32.16) 27.46,32.76 R9.1
  BOTTOM w0.127: v1(96.79,8.92) 96.66,8.79 95.34,8.79 95.12,9.01 93.68,9.01 93.22,8.55 87.4,8.55 84.65,11.3 84.65,13.49 83.5,14.64 83.41,14.64 77.8,20.25 77.33,20.25 v1(77.07,19.99) 75.71,18.63 70.59,18.63 68.1,21.11 65.47,21.11 63.41,23.18 43.57,23.18 40.98,25.78 40.98,27.7 36.42,32.26 32.27,32.26 31.55,32.98 27.68,32.98 v1(26.87,32.16) 25.98,33.05 23.81,33.05 21.62,35.24 21.62,38.26 17.69,42.2 16.9,42.2 16.29,42.81 v1(16.29,43.47)
PMIC_PWRON: length 114.1
  TOP w0.127: M1.4 86.3,22.19 87.28,23.17 v1(87.28,23.79)
  BOTTOM w0.127: R267.1 131.45,81.65 131.45,79.84 131.12,79.51 128.28,79.51 125.98,77.21 125.98,71.63 129.53,68.08 130.64,68.08 131.32,67.4 131.32,45.6 127.41,41.69 127.41,41.4 127.19,41.17 127.19,40.32 125.76,38.89 125.76,33.35 124.35,31.94 124.35,30.38 124.54,30.19 124.54,27.25 115.94,18.66 110.23,18.66 110.08,18.5 103.29,18.5 102.92,18.87 92.54,18.87 87.62,23.79 v1(87.28,23.79)
PMIC_SLEEP_H: length 69.8
  TOP w0.127: v1(34.24,32.72) 34.24,33.97 R1083.1 ; v1(76.36,20.09) 76.72,20.45 79.51,20.45 80.17,21.11 80.17,25.56 81.24,26.63 81.24,32.72 81.7,33.19 M1.15
  BOTTOM w0.127: v1(76.36,20.09) 75.23,18.96 70.77,18.96 68.36,21.37 65.58,21.37 63.51,23.43 43.68,23.43 41.23,25.89 41.23,27.8 36.52,32.51 34.45,32.51 v1(34.24,32.72)
PMIC_VDC: length 9.1
  TOP w0.254: M1.5 83.26,23.19 83.9,22.54 86.16,22.54 86.73,23.1 R17.1 C302.2 R389.2
PWRON_KEY: length 5.3
  BOTTOM w0.127: R267.2 132.08,83.03 D51.1 132.11,86.65 SW4.1
RECOVERY_KEY: length 11.6
  TOP w0.203: R264.2 75.79,82.91 75.82,82.94 D46.1 78.24,82.94 79.53,84.23 81.34,84.23 v1(83.6,86.49)
  BOTTOM w0.203: v1(83.6,86.49) SW5.4
REFCLKN_100M_RJ45: length 21
  TOP w0.102: v1(83.65,57.88) 83.65,57.92 83.89,58.16 85.44,58.16 86.03,57.57 86.03,52.81 88.36,50.48 88.62,50.48 88.86,50.24 88.86,50.12 88.75,50.01 R404.2
  BOTTOM w0.102: v1(83.65,57.88) 83.65,57.92 83.42,58.16 83.26,58.16 82.03,56.93 81.03,56.93 80.87,56.77 79.19,56.77 78.79,57.16 76.36,57.16 76.25,57.05 U15.16
REFCLKP_100M_RJ45: length 21
  TOP w0.102: v1(83.65,58.69) 83.93,58.41 85.55,58.41 86.29,57.67 86.29,52.91 88.47,50.73 88.72,50.73 R403.2
  BOTTOM w0.102: U15.15 76.25,57.45 76.29,57.41 78.9,57.41 79.29,57.02 80.77,57.02 80.93,57.18 81.92,57.18 83.15,58.41 83.38,58.41 v1(83.65,58.69)
RESET_KEY: length 11.5
  TOP w0.127: v1(129.06,35.47) 127.44,35.47 D50.1 127.38,35.41 R266.2
  BOTTOM w0.127: v1(129.06,35.47) 129.06,39.66 131.44,42.03 SW6.4
RESETN: length 65.2
  TOP w0.127: v1(92.36,33.35) 92.6,33.59 101.66,33.59 v1(102.14,33.11) ; R36.1 102.78,41.99 102.78,39.91 v1(102.39,39.53) 104.17,37.75 107.17,37.75 109.68,35.24 112.78,35.24 113.7,36.15 121.78,36.15 123.65,34.27 126.04,34.27 R266.1 ; v1(90.08,30.39) 88.04,28.35 86.9,28.35 86.19,27.64 86.19,23.1 85.95,22.85 84.04,22.85 82.7,24.19 M1.6
  BOTTOM w0.127: v1(102.14,33.11) 102.56,33.53 102.56,39.36 v1(102.39,39.53) ; v1(92.36,33.35) 90.08,31.06 v1(90.08,30.39)
RGMII_CLK_M0: length 41.3
  TOP w0.127: 37.57,33.19 37.99,33.19 38.46,33.66 38.46,35.26 39.82,36.62 39.82,40.89 41.87,42.94 51.64,42.94 v1(52.71,44.01)
  BOTTOM w0.127: v1(52.71,44.01) 52.36,44.01 50.45,45.91 49.09,45.91 46.23,48.76 46.23,50.02 45.6,50.65 45.6,53.93 C130.2 R171.2 46.16,55.5 47.45,55.5 47.67,55.28 R170.1
RGMII_MDC_M0: length 47.5
  TOP w0.127: v1(54.81,44.11) 53.99,44.94 52.24,44.94 50.98,43.68 41.53,43.68 39.11,41.26 39.03,41.14 38.39,38.7 37.88,38.19 37.57,38.19
  BOTTOM w0.127: U16.13 57.59,58.31 58.91,57.95 60.77,57.95 63.05,55.67 63.68,54.64 64.23,54.1 64.23,48 60.76,44.54 59.82,44.31 55.88,44.31 v1(54.81,44.11)
RGMII_MDIO_M0: length 46.4
  TOP w0.127: v1(54.13,44.1) 53.6,44.64 52.46,44.64 51.19,43.37 41.71,43.37 39.33,40.98 39.33,38.46 38.05,37.19 37.57,37.19
  BOTTOM w0.127: v1(54.13,44.1) 54.13,44.2 54.54,44.61 59.47,44.61 63.42,48.56 63.42,53.81 62.26,54.96 62.26,55.33 60.66,56.93 59.78,56.93 R191.1 58.3,57.44 57.83,57.91 U16.14
RGMII_RXCLK_M0: length 31.5
  TOP w0.127: 37.57,47.19 38,47.19 38.47,46.71 50.06,46.71 v1(50.27,46.5)
  BOTTOM w0.127: v1(50.27,46.5) 50.27,47.03 49.86,47.43 48.57,47.43 48.26,47.75 48.26,48.56 48.41,48.72 48.66,48.72 48.76,48.61 48.76,48.07 48.89,47.94 49.15,47.94 49.27,48.07 49.27,48.52 49.4,48.65 49.65,48.65 49.78,48.52 49.78,48.07 49.91,47.94 50.16,47.94 50.29,48.07 50.29,48.54 50.42,48.67 50.67,48.67 50.8,48.54 50.8,48.07 50.92,47.94 51.18,47.94 51.3,48.07 51.3,48.52 51.43,48.65 51.69,48.65 51.81,48.52 51.81,48.07 51.94,47.94 52.19,47.94 52.32,48.07 52.32,48.52 52.45,48.65 52.7,48.65 52.83,48.52 52.83,48.07 52.96,47.94 53.28,47.94 55.21,49.87 C143.2 55.21,50.65 55.02,50.83 R192.2
RGMII_RXD0_M0: length 33.9
  TOP w0.127: v1(52.7,45.91) 52.13,45.91 51.34,45.12 49.86,45.12 49.74,44.99 49.74,44.58 49.61,44.46 49.36,44.46 49.23,44.58 49.23,44.99 49.1,45.12 48.85,45.12 48.72,44.99 48.72,44.58 48.59,44.46 48.34,44.46 48.21,44.58 48.21,44.99 48.09,45.12 47.83,45.12 47.71,44.99 47.71,44.58 47.58,44.46 47.32,44.46 47.2,44.58 47.2,44.99 47.07,45.12 41.24,45.12 39.31,43.19 37.57,43.19
  BOTTOM w0.127: v1(52.7,45.91) 52.7,46.07 55.76,49.13 57.01,49.13 57.59,49.72 57.59,50.02 58.33,50.76 58.33,52.36 58.13,52.55 R182.1 R181.2 56.46,53.02 56.01,53.02 54.59,54.44 U16.25
RGMII_RXD1_M0: length 34.3
  TOP w0.127: 37.57,42.19 38.71,42.19 41.38,44.86 45.22,44.86 45.9,44.19 50.77,44.19 52.03,45.45 52.94,45.45 v1(53.37,45.88)
  BOTTOM w0.127: U16.24 54.99,54.42 56.14,53.27 56.57,53.27 56.82,53.02 58.37,53.02 R184.2 59.2,52.55 59.38,52.37 59.38,50.64 59.16,50.41 R185.1 59.16,49.25 58.7,48.79 57.15,48.79 56.27,47.91 55.33,47.91 54.49,47.07 54.22,47.07 53.37,46.23 v1(53.37,45.88)
RGMII_RXD2_M0: length 34.6
  TOP w0.127: 37.57,49.19 38.32,49.19 38.53,48.98 40.13,48.98 v1(40.42,49.27) 40.81,49.27 42.64,47.45 v1(55.66,47.45)
  BOTTOM w0.127: v1(55.66,47.45) 56.22,47.45 57.31,48.54 58.9,48.54 59.64,49.28 59.64,52.67 59.04,53.27 56.93,53.27 56.32,53.88 55.91,53.88 55.39,54.4 U16.23 ; R188.1 R187.2 40.74,49.59 v1(40.42,49.27)
RGMII_RXD3_M0: length 34.7
  TOP w0.127: v1(55.15,46.94) 54.94,47.15 39.07,47.15 38.04,48.19 37.57,48.19
  BOTTOM w0.127: v1(55.15,46.94) 56.18,46.94 57.53,48.29 58.21,48.29 58.73,47.76 59.44,47.76 60.61,48.94 60.61,52.36 60.42,52.55 R178.1 60.1,52.99 58.96,54.13 56.04,54.13 55.79,54.39 U16.22
RGMII_RXDV_M0: length 34.5
  TOP w0.127: v1(54.44,45.14) 54.39,45.19 52.13,45.19 50.87,43.93 45.79,43.93 45.11,44.61 41.69,44.61 38.26,41.19 37.57,41.19
  BOTTOM w0.127: U16.26 54.19,54.4 55.91,52.68 R180.2 56.22,52.55 56.42,52.36 56.42,50.71 56.66,50.46 56.66,49.72 56.43,49.49 55.51,49.49 52.18,46.16 52.18,45.7 52.74,45.14 v1(54.44,45.14)
RGMII_TXCLK_M0: length 2.6
  TOP w0.127: 37.57,50.19 38.63,50.19 v1(39.02,50.58)
  BOTTOM w0.127: R177.1 39.4,50.96 v1(39.02,50.58)
RGMII_TXD0_M0: length 38.3
  TOP w0.127: 37.57,46.19 49.75,46.19 50.05,45.88 51.02,45.88 52.04,46.9 54.54,46.9 54.96,46.47 55.9,46.47 v1(56.37,46)
  BOTTOM w0.127: v1(56.37,46) 56.84,46.47 59.82,46.47 62.35,49.01 62.35,53.33 61.22,54.46 61.22,54.85 60.29,55.79 58.36,55.79 57.84,56.31 U16.18
RGMII_TXD1_M0: length 39.5
  TOP w0.127: v1(55.02,45.88) 54.26,46.64 52.15,46.64 51.13,45.63 39.02,45.63 38.58,45.19 37.57,45.19
  BOTTOM w0.127: v1(55.02,45.88) 55.38,45.52 56.54,45.52 57.24,46.22 59.92,46.22 62.61,48.9 62.61,53.46 61.47,54.6 61.47,54.96 60.39,56.04 58.47,56.04 57.8,56.71 U16.17
RGMII_TXD2_M0: length 42.2
  TOP w0.127: 37.57,52.19 38.13,52.19 38.62,51.69 39.15,51.69 42.89,47.96 50.66,47.96 50.87,48.17 55.96,48.17 58.53,45.59 v1(58.53,45.5)
  BOTTOM w0.127: v1(58.53,45.5) 59.56,45.5 62.86,48.8 62.86,53.57 61.73,54.7 61.73,55.06 60.5,56.29 58.57,56.29 57.76,57.11 U16.16
RGMII_TXD3_M0: length 43.6
  TOP w0.127: v1(57.18,45.5) 57.18,46.58 55.85,47.91 50.98,47.91 50.77,47.7 42.74,47.7 39.25,51.19 37.57,51.19
  BOTTOM w0.127: v1(57.18,45.5) 57.66,45.02 59.44,45.02 63.11,48.69 63.11,53.67 61.98,54.81 61.98,55.17 60.6,56.55 58.68,56.55 57.72,57.51 U16.15
RGMII_TXEN_M0: length 37.9
  TOP w0.127: 37.57,44.19 39.03,44.19 40.22,45.37 51.23,45.37 52.25,46.39 53.7,46.39 54.05,46.04 v1(54.05,45.88)
  BOTTOM w0.127: U16.19 57.88,55.91 58.26,55.53 60.18,55.53 60.97,54.75 60.97,54.36 62.1,53.23 62.1,49.11 59.71,46.73 56.66,46.73 56.52,46.59 55.68,46.59 55.57,46.47 54.64,46.47 v1(54.05,45.88)
RMII_CLK: length 60.3
  TOP w0.127: M1.36 81.63,54.19 81.14,54.68 v1(81.14,54.72)
  BOTTOM w0.127: R213.1 C155.2 39.6,52.31 38.39,51.09 38.39,49.44 39.15,48.68 44.42,48.68 50.57,42.53 60.76,42.53 65.94,47.7 74.88,47.7 76.13,48.95 76.79,48.95 77.54,49.7 77.54,51.07 78.26,51.8 78.26,53.82 79.41,54.97 79.86,54.97 80.16,54.67 81.09,54.67 v1(81.14,54.72)
RMII_CLK_: length 2.7
  BOTTOM w0.127: U17.15 36.97,56.06 38.01,55.02 R213.2
RMII_CLK_CTL: length 2.3
  BOTTOM w0.127: U17.12 38.58,57.56 R216.1
RMII_CRS_DV: length 67.2
  TOP w0.127: M1.35 81.76,53.19 81.06,52.48 81.06,51.44 78.53,48.91 78.53,47.02 v1(77.87,46.37)
  BOTTOM w0.127: v1(77.87,46.37) 77.33,46.37 76.51,45.55 66.72,45.55 61.66,40.49 49.73,40.49 43.57,46.64 38.3,46.64 36.15,48.8 33.28,48.8 29.73,52.35 29.12,52.35 28.54,52.93 28.54,53.37 R1198.2 R215.1
RMII_CRS_DVALID: length 2.9
  BOTTOM w0.127: U17.26 31.11,56.06 R215.2
RMII_MDC: length 8.5
  TOP w0.127: M1.42 82.6,60.19 83.06,59.73 83.06,56.81 83.99,55.88 83.99,54.74 v1(83.53,54.28)
  BOTTOM w0.127: R203.1 82.8,54.33 82.85,54.28 v1(83.53,54.28)
